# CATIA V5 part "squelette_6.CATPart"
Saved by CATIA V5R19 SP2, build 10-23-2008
Part number: squelette_6
Publications: "Point.1", "Point.2", "Point.3", "Point.4", "Point.5", "Droite.1", "Droite.2", "Droite.3", "Droite.4", "Droite.5", "Droite.6", "Droite.7"
Bounding box of the stored display mesh (mm): x -10 to 10, y -98 to 70, z -3 to 3
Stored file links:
  M:\EU_thinkMotion\IAO_2010\iao\IAO_MMS_Groupe2\IAO_MMS_Groupe2\sdubois\sdubois\sdubois\IAO_mecanisme\squelette_6.CATPart
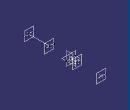
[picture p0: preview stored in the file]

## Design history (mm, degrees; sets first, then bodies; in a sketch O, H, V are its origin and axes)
Set1
  Point1: (0, 0, 0)
  Point2: (0, 70, 0)
  Point3: (0, -50, 0)
  Point4: (0, 14, 0)
  Point5: (0, -98, 0)
  Line1: type PtDir, RefPoint Point2, Direction yz-plane, Start -10, End 10
  Line2: type PtDir, RefPoint Point4, Direction yz-plane, Start -10, End 10
  Line3: type PtDir, RefPoint Point1, Direction yz-plane, Start -10, End 10
  Line4: type PtDir, RefPoint Point3, Direction yz-plane, Start -10, End 10
  Line5: type PtDir, RefPoint Point5, Direction yz-plane, Start -10, End 10
  Line6: type PtPt, FirstPoint Point5, SecondPoint Point3
  Line7: type PtPt, FirstPoint Point1, SecondPoint Point4
  Point6: (0, 0, 3)
  Point7: (0, 0, -3)
  Plane1: type OffsetPt, RefPlane zx-plane, RefPoint Point5
  Plane2: type OffsetPt, RefPlane zx-plane, RefPoint Point3
  Plane3: type OffsetPt, RefPlane zx-plane, RefPoint Point4
  Plane4: type OffsetPt, RefPlane zx-plane, RefPoint Point2
Body1 (main body)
